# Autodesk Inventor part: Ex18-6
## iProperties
Author: Elise Moss
Revision Number: A
Created: 2001-09
Part Number: Ex18-6
Description: PLATE, JAW
Document SubType Name: Modeling
Designer: Elise Moss
Control State: 0
Master: False
Checked Out: False
PropertySet Name: Design Tracking Control
Length Units: 11272
Angle Units: 11279
Time Units: 11290
Mass Units: 11286
Shininess: 3
Angle Display Precision: 2
Document Length Units: 11272
Document Angle Units: 11286
Document Time Units: 11279
Document Mass Units: 11290
Document Length Units Precision: 3
Document Angle Units Precision: 0
Compacted: False
PropertySet Name: _Private Model Information
Density: 0.0
Volumn: 0.0
Area: 0.0
PropertySet Name: Model Information
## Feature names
1. Extrusion1
2. Hole1
3. Chamfer1
